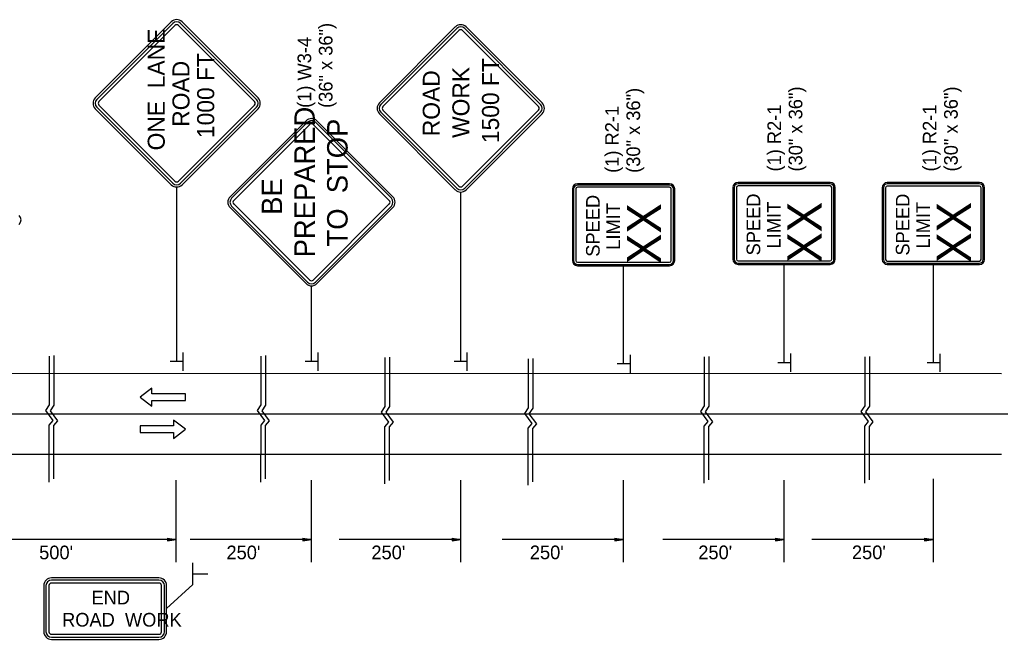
# Model space of a CAD drawing. Extents: x 1927831 to 1930787, y 596452 to 597699.
# Drawn here: x 1928053.9 to 1928485.3, y 596920.4 to 597192.8 of the extents above; entities that cross this region are included whole.
import ezdxf

# ---------------------------------------------------------------- set-up
doc = ezdxf.new("R2010")
doc.units = 0
for name, color, linetype in [('Default', 7, 'Continuous'), ('P_TC_Signs_Permanent', 7, 'Continuous'), ('P_TC_Signs_Temporary', 7, 'Continuous'), ('R_Annotation', 7, 'Continuous'), ('R_Striping', 7, 'Continuous')]:
    doc.layers.add(name, color=color, linetype=linetype)

msp = doc.modelspace()

# ---------------------------------------------------------------- linework, layer by layer
at = {"layer": 'Default'}
for p, q in [((1928125.67, 597046.42), (1928125.67, 597038.42)), ((1928185.12, 597046.42), (1928185.12, 597038.42)), ((1928250.6, 597046.42), (1928250.6, 597038.42)), ((1928322.37, 597045.39), (1928322.37, 597037.38)), ((1928392.98, 597045.97), (1928392.98, 597037.96)), ((1928458.63, 597045.91), (1928458.63, 597037.91)), ((1928125.55, 597042.44), (1928120.09, 597042.44)), ((1928185.01, 597042.44), (1928179.54, 597042.44)), ((1928250.48, 597042.44), (1928245.02, 597042.44)), ((1928322.25, 597041.41), (1928316.79, 597041.41)), ((1928392.86, 597041.99), (1928387.4, 597041.99)), ((1928458.51, 597041.93), (1928453.05, 597041.93)), ((1927841.07, 597037.34), (1928485.68, 597037.29)), ((1927840.35, 597019.55), (1928622.79, 597019.49)), ((1927840.85, 597001.76), (1928485.68, 597001.71)), ((1928122.82, 596954.25), (1928122.82, 596990.28)), ((1928182.27, 596954.25), (1928182.27, 596990.28)), ((1928247.93, 596954.25), (1928247.93, 596990.28)), ((1928319.52, 596954.25), (1928319.52, 596990.28)), ((1928390.13, 596954.25), (1928390.13, 596990.28)), ((1928455.78, 596954.25), (1928455.78, 596990.96)), ((1928122.82, 596964.29), (1928023.06, 596964.29)), ((1928118.98, 596964.87), (1928122.82, 596964.29)), ((1928118.98, 596964.87), (1928118.98, 596963.71)), ((1928118.98, 596964.77), (1928122.18, 596964.29)), ((1928118.98, 596964.67), (1928121.52, 596964.29)), ((1928118.98, 596964.58), (1928120.88, 596964.29)), ((1928118.98, 596964.48), (1928120.23, 596964.29)), ((1928118.98, 596964.38), (1928119.59, 596964.29)), ((1928118.98, 596963.71), (1928122.82, 596964.29)), ((1928118.98, 596964.1), (1928120.23, 596964.29)), ((1928118.98, 596963.91), (1928121.52, 596964.29)), ((1928118.98, 596963.81), (1928122.18, 596964.29)), ((1928118.98, 596964), (1928120.88, 596964.29)), ((1928118.98, 596964.2), (1928119.59, 596964.29)), ((1928182.27, 596964.29), (1928128.87, 596964.29)), ((1928178.44, 596964.87), (1928182.27, 596964.29)), ((1928178.44, 596964.87), (1928178.44, 596963.71)), ((1928178.44, 596964.77), (1928181.63, 596964.29)), ((1928178.44, 596964.67), (1928180.97, 596964.29)), ((1928178.44, 596964.58), (1928180.33, 596964.29)), ((1928178.44, 596964.48), (1928179.68, 596964.29)), ((1928178.44, 596964.38), (1928179.04, 596964.29)), ((1928178.44, 596963.71), (1928182.27, 596964.29)), ((1928178.44, 596964.1), (1928179.68, 596964.29)), ((1928178.44, 596963.91), (1928180.97, 596964.29)), ((1928178.44, 596963.81), (1928181.63, 596964.29)), ((1928178.44, 596964), (1928180.33, 596964.29)), ((1928178.44, 596964.2), (1928179.04, 596964.29)), ((1928247.93, 596964.29), (1928194.52, 596964.29)), ((1928244.09, 596964.87), (1928247.93, 596964.29)), ((1928244.09, 596964.87), (1928244.09, 596963.71)), ((1928244.09, 596964.77), (1928247.29, 596964.29)), ((1928244.09, 596964.67), (1928246.63, 596964.29)), ((1928244.09, 596964.58), (1928245.99, 596964.29)), ((1928244.09, 596964.48), (1928245.34, 596964.29)), ((1928244.09, 596964.38), (1928244.7, 596964.29)), ((1928244.09, 596963.71), (1928247.93, 596964.29)), ((1928244.09, 596964.1), (1928245.34, 596964.29)), ((1928244.09, 596963.91), (1928246.63, 596964.29)), ((1928244.09, 596963.81), (1928247.29, 596964.29)), ((1928244.09, 596964), (1928245.99, 596964.29)), ((1928244.09, 596964.2), (1928244.7, 596964.29)), ((1928319.52, 596964.29), (1928266.12, 596964.29)), ((1928315.68, 596964.87), (1928319.52, 596964.29)), ((1928315.68, 596964.87), (1928315.68, 596963.71)), ((1928315.68, 596964.77), (1928318.88, 596964.29)), ((1928315.68, 596964.67), (1928318.22, 596964.29)), ((1928315.68, 596964.58), (1928317.58, 596964.29)), ((1928315.68, 596964.48), (1928316.93, 596964.29)), ((1928315.68, 596964.38), (1928316.29, 596964.29)), ((1928315.68, 596963.71), (1928319.52, 596964.29)), ((1928315.68, 596964.1), (1928316.93, 596964.29)), ((1928315.68, 596963.91), (1928318.22, 596964.29)), ((1928315.68, 596963.81), (1928318.88, 596964.29)), ((1928315.68, 596964), (1928317.58, 596964.29)), ((1928315.68, 596964.2), (1928316.29, 596964.29)), ((1928390.13, 596964.29), (1928336.73, 596964.29)), ((1928386.29, 596964.87), (1928390.13, 596964.29)), ((1928386.29, 596964.87), (1928386.29, 596963.71)), ((1928386.29, 596964.77), (1928389.49, 596964.29)), ((1928386.29, 596964.67), (1928388.83, 596964.29)), ((1928386.29, 596964.58), (1928388.19, 596964.29)), ((1928386.29, 596964.48), (1928387.54, 596964.29)), ((1928386.29, 596964.38), (1928386.9, 596964.29)), ((1928386.29, 596963.71), (1928390.13, 596964.29)), ((1928386.29, 596964.1), (1928387.54, 596964.29)), ((1928386.29, 596963.91), (1928388.83, 596964.29)), ((1928386.29, 596963.81), (1928389.49, 596964.29)), ((1928386.29, 596964), (1928388.19, 596964.29)), ((1928386.29, 596964.2), (1928386.9, 596964.29)), ((1928455.78, 596964.29), (1928402.38, 596964.29)), ((1928451.94, 596964.87), (1928455.78, 596964.29)), ((1928451.94, 596964.87), (1928451.94, 596963.71)), ((1928451.94, 596964.77), (1928455.14, 596964.29)), ((1928451.94, 596964.67), (1928454.48, 596964.29)), ((1928451.94, 596964.58), (1928453.84, 596964.29)), ((1928451.94, 596964.48), (1928453.19, 596964.29)), ((1928451.94, 596964.38), (1928452.55, 596964.29)), ((1928451.94, 596963.71), (1928455.78, 596964.29)), ((1928451.94, 596964.1), (1928453.19, 596964.29)), ((1928451.94, 596963.91), (1928454.48, 596964.29)), ((1928451.94, 596963.81), (1928455.14, 596964.29)), ((1928451.94, 596964), (1928453.84, 596964.29)), ((1928451.94, 596964.2), (1928452.55, 596964.29)), ((1928130.08, 596944.51), (1928130.08, 596954)), ((1928130.22, 596949.23), (1928136.7, 596949.23)), ((1928130.08, 596944.51), (1928118.55, 596933.86))]:
    msp.add_line(p, q, dxfattribs=at)
for points in [[(1928066.89, 597044.92), (1928066.89, 597023.4), (1928065.23, 597020.93), (1928068.47, 597016.5), (1928066.76, 597014.45), (1928066.76, 596989.43)], [(1928068.93, 597045.12), (1928068.93, 597023.32), (1928067.27, 597020.84), (1928070.51, 597016.41), (1928068.81, 597014.37), (1928068.8, 596990.87)], [(1928160.05, 597044.92), (1928160.05, 597023.4), (1928158.39, 597020.93), (1928161.63, 597016.5), (1928159.93, 597014.45), (1928159.92, 596989.43)], [(1928162.1, 597045.12), (1928162.1, 597023.32), (1928160.44, 597020.84), (1928163.67, 597016.41), (1928161.97, 597014.37), (1928161.97, 596990.87)], [(1928214.52, 597044.28), (1928214.52, 597022.75), (1928212.85, 597020.28), (1928216.09, 597015.85), (1928214.39, 597013.81), (1928214.38, 596988.78)], [(1928216.56, 597044.47), (1928216.56, 597022.67), (1928214.9, 597020.2), (1928218.14, 597015.77), (1928216.43, 597013.72), (1928216.43, 596990.22)], [(1928277.56, 597043.61), (1928277.56, 597022.08), (1928275.9, 597019.61), (1928279.13, 597015.18), (1928277.43, 597013.14), (1928277.42, 596988.11)], [(1928279.6, 597043.8), (1928279.6, 597022), (1928277.94, 597019.53), (1928281.18, 597015.1), (1928279.47, 597013.05), (1928279.47, 596989.55)], [(1928355, 597044.49), (1928355, 597022.97), (1928353.34, 597020.5), (1928356.57, 597016.07), (1928354.87, 597014.02), (1928354.86, 596989)], [(1928357.04, 597044.69), (1928357.04, 597022.88), (1928355.38, 597020.41), (1928358.62, 597015.98), (1928356.91, 597013.94), (1928356.91, 596990.44)], [(1928425.61, 597044.49), (1928425.61, 597022.97), (1928423.95, 597020.5), (1928427.18, 597016.07), (1928425.48, 597014.02), (1928425.47, 596989)], [(1928427.65, 597044.69), (1928427.65, 597022.88), (1928425.99, 597020.41), (1928429.23, 597015.98), (1928427.52, 597013.94), (1928427.52, 596990.44)]]:
    msp.add_lwpolyline(points, dxfattribs=at)
at = {"layer": 'P_TC_Signs_Permanent'}
for p, q in [((1928179.89, 597148.33), (1928146.48, 597114.92)), ((1928180.55, 597147.67), (1928147.14, 597114.25)), ((1928181.48, 597146.74), (1928148.07, 597113.33)), ((1928216.48, 597113.33), (1928183.07, 597146.74)), ((1928217.41, 597114.25), (1928184, 597147.67)), ((1928218.07, 597114.92), (1928184.66, 597148.33)), ((1928339.77, 597120.63), (1928299.27, 597120.63)), ((1928339.77, 597120.07), (1928299.27, 597120.07)), ((1928339.77, 597119.13), (1928299.27, 597119.13)), ((1928367.63, 597118.96), (1928367.63, 597087.46)), ((1928368.19, 597118.96), (1928368.19, 597087.46)), ((1928369.13, 597118.96), (1928369.13, 597087.46)), ((1928410.38, 597121.21), (1928369.88, 597121.21)), ((1928410.38, 597120.65), (1928369.88, 597120.65)), ((1928410.38, 597119.71), (1928369.88, 597119.71)), ((1928411.13, 597087.46), (1928411.13, 597118.96)), ((1928412.07, 597087.46), (1928412.07, 597118.96)), ((1928412.63, 597087.46), (1928412.63, 597118.96)), ((1928433.28, 597118.9), (1928433.28, 597087.4)), ((1928433.84, 597118.9), (1928433.84, 597087.4)), ((1928434.78, 597118.9), (1928434.78, 597087.4)), ((1928476.03, 597121.15), (1928435.53, 597121.15)), ((1928476.03, 597120.59), (1928435.53, 597120.59)), ((1928476.03, 597119.65), (1928435.53, 597119.65)), ((1928476.78, 597087.4), (1928476.78, 597118.9)), ((1928477.72, 597087.4), (1928477.72, 597118.9)), ((1928478.28, 597087.4), (1928478.28, 597118.9)), ((1928297.02, 597118.38), (1928297.02, 597086.88)), ((1928297.58, 597118.38), (1928297.58, 597086.88)), ((1928298.52, 597118.38), (1928298.52, 597086.88)), ((1928340.52, 597086.88), (1928340.52, 597118.38)), ((1928341.46, 597086.88), (1928341.46, 597118.38)), ((1928342.02, 597086.88), (1928342.02, 597118.38)), ((1928146.48, 597110.14), (1928179.89, 597076.73)), ((1928147.14, 597110.81), (1928180.55, 597077.4)), ((1928148.07, 597111.74), (1928181.48, 597078.32)), ((1928183.07, 597078.32), (1928216.48, 597111.74)), ((1928184, 597077.4), (1928217.41, 597110.81)), ((1928184.66, 597076.73), (1928218.07, 597110.14)), ((1928299.27, 597086.13), (1928339.77, 597086.13)), ((1928299.27, 597085.19), (1928339.77, 597085.19)), ((1928299.27, 597084.63), (1928339.77, 597084.63)), ((1928369.88, 597086.71), (1928410.38, 597086.71)), ((1928369.88, 597085.77), (1928410.38, 597085.77)), ((1928369.88, 597085.21), (1928410.38, 597085.21)), ((1928435.53, 597086.65), (1928476.03, 597086.65)), ((1928435.53, 597085.71), (1928476.03, 597085.71)), ((1928435.53, 597085.15), (1928476.03, 597085.15))]:
    msp.add_line(p, q, dxfattribs=at)
for centre, radius, start, end in [((1928182.27, 597145.94), 3.37, 45, 135), ((1928182.27, 597145.94), 2.44, 45, 135), ((1928182.27, 597145.94), 1.13, 45, 135), ((1928299.27, 597118.38), 2.25, 90, 180), ((1928299.27, 597118.38), 1.69, 90, 180), ((1928299.27, 597118.38), 0.75, 90, 180), ((1928339.77, 597118.38), 2.25, 360, 90), ((1928339.77, 597118.38), 1.69, 360, 90), ((1928339.77, 597118.38), 0.75, 360, 90), ((1928369.88, 597118.96), 2.25, 90, 180), ((1928369.88, 597118.96), 1.69, 90, 180), ((1928369.88, 597118.96), 0.75, 90, 180), ((1928410.38, 597118.96), 2.25, 360, 90), ((1928410.38, 597118.96), 1.69, 360, 90), ((1928410.38, 597118.96), 0.75, 360, 90), ((1928435.53, 597118.9), 2.25, 90, 180), ((1928435.53, 597118.9), 1.69, 90, 180), ((1928435.53, 597118.9), 0.75, 90, 180), ((1928476.03, 597118.9), 2.25, 360, 90), ((1928476.03, 597118.9), 1.69, 360, 90), ((1928476.03, 597118.9), 0.75, 360, 90), ((1928148.86, 597112.53), 3.37, 135, 225), ((1928215.68, 597112.53), 3.37, 315, 45), ((1928148.86, 597112.53), 2.44, 135, 225), ((1928148.86, 597112.53), 1.13, 135, 225), ((1928215.68, 597112.53), 1.13, 315, 45), ((1928215.68, 597112.53), 2.44, 315, 45), ((1928051.76, 597104.75), 2.81, 315, 45), ((1928299.27, 597086.88), 2.25, 180, 270), ((1928299.27, 597086.88), 1.69, 180, 270), ((1928299.27, 597086.88), 0.75, 180, 270), ((1928339.77, 597086.88), 2.25, 270, 360), ((1928339.77, 597086.88), 1.69, 270, 360), ((1928339.77, 597086.88), 0.75, 270, 360), ((1928369.88, 597087.46), 2.25, 180, 270), ((1928369.88, 597087.46), 1.69, 180, 270), ((1928369.88, 597087.46), 0.75, 180, 270), ((1928410.38, 597087.46), 2.25, 270, 360), ((1928410.38, 597087.46), 1.69, 270, 360), ((1928410.38, 597087.46), 0.75, 270, 360), ((1928435.53, 597087.4), 2.25, 180, 270), ((1928435.53, 597087.4), 1.69, 180, 270), ((1928435.53, 597087.4), 0.75, 180, 270), ((1928476.03, 597087.4), 2.25, 270, 360), ((1928476.03, 597087.4), 1.69, 270, 360), ((1928476.03, 597087.4), 0.75, 270, 360), ((1928182.27, 597079.12), 3.37, 225, 315), ((1928182.27, 597079.12), 2.44, 225, 315), ((1928182.27, 597079.12), 1.13, 225, 315)]:
    msp.add_arc(centre, radius, start, end, dxfattribs=at)
at = {"layer": 'P_TC_Signs_Temporary'}
for p, q in [((1928087.2, 597158.38), (1928120.61, 597191.8)), ((1928087.86, 597157.72), (1928121.27, 597191.13)), ((1928088.79, 597156.79), (1928122.2, 597190.2)), ((1928123.79, 597190.2), (1928157.2, 597156.79)), ((1928124.72, 597191.13), (1928158.13, 597157.72)), ((1928125.38, 597191.8), (1928158.79, 597158.38)), ((1928212.13, 597156.16), (1928245.54, 597189.57)), ((1928212.79, 597155.5), (1928246.2, 597188.91)), ((1928213.72, 597154.57), (1928247.13, 597187.98)), ((1928248.72, 597187.98), (1928282.13, 597154.57)), ((1928249.65, 597188.91), (1928283.06, 597155.5)), ((1928250.31, 597189.57), (1928283.72, 597156.16)), ((1928120.61, 597120.2), (1928087.2, 597153.61)), ((1928121.27, 597120.86), (1928087.86, 597154.27)), ((1928122.2, 597121.79), (1928088.79, 597155.2)), ((1928157.2, 597155.2), (1928123.79, 597121.79)), ((1928158.13, 597154.27), (1928124.72, 597120.86)), ((1928158.79, 597153.61), (1928125.38, 597120.2)), ((1928245.54, 597117.98), (1928212.13, 597151.39)), ((1928246.2, 597118.64), (1928212.79, 597152.05)), ((1928247.13, 597119.57), (1928213.72, 597152.98)), ((1928282.13, 597152.98), (1928248.72, 597119.57)), ((1928283.06, 597152.05), (1928249.65, 597118.64)), ((1928283.72, 597151.39), (1928250.31, 597117.98)), ((1928115.18, 596947.36), (1928067.93, 596947.36)), ((1928115.18, 596946.42), (1928067.93, 596946.42)), ((1928064.55, 596943.99), (1928064.55, 596923.74)), ((1928065.49, 596943.99), (1928065.49, 596923.74)), ((1928066.8, 596943.99), (1928066.8, 596923.74)), ((1928115.18, 596945.11), (1928067.93, 596945.11)), ((1928116.3, 596923.74), (1928116.3, 596943.99)), ((1928117.61, 596923.74), (1928117.61, 596943.99)), ((1928118.55, 596923.74), (1928118.55, 596943.99)), ((1928067.93, 596922.61), (1928115.18, 596922.61)), ((1928067.93, 596921.3), (1928115.18, 596921.3)), ((1928067.93, 596920.36), (1928115.18, 596920.36))]:
    msp.add_line(p, q, dxfattribs=at)
for centre, radius, start, end in [((1928122.99, 597189.41), 3.37, 45, 135), ((1928122.99, 597189.41), 2.44, 45, 135), ((1928122.99, 597189.41), 1.12, 45, 135), ((1928247.93, 597187.19), 3.37, 45, 135), ((1928247.93, 597187.19), 2.44, 45, 135), ((1928247.93, 597187.19), 1.12, 45, 135), ((1928089.58, 597156), 3.37, 135, 225), ((1928089.58, 597156), 2.44, 135, 225), ((1928156.4, 597156), 2.44, 315, 45), ((1928156.4, 597156), 3.37, 315, 45), ((1928089.58, 597156), 1.13, 135, 225), ((1928156.4, 597156), 1.13, 315, 45), ((1928214.52, 597153.78), 3.37, 135, 225), ((1928214.52, 597153.78), 2.44, 135, 225), ((1928214.52, 597153.78), 1.13, 135, 225), ((1928281.34, 597153.78), 1.13, 315, 45), ((1928281.34, 597153.78), 2.44, 315, 45), ((1928281.34, 597153.78), 3.37, 315, 45), ((1928122.99, 597122.59), 3.37, 225, 315), ((1928122.99, 597122.59), 2.44, 225, 315), ((1928122.99, 597122.59), 1.12, 225, 315), ((1928247.93, 597120.37), 2.44, 225, 315), ((1928247.93, 597120.37), 1.12, 225, 315), ((1928247.93, 597120.37), 3.37, 225, 315), ((1928067.93, 596943.99), 3.37, 90, 180), ((1928067.93, 596943.99), 2.44, 90, 180), ((1928115.18, 596943.99), 3.38, 0, 90), ((1928115.18, 596943.99), 2.44, 0, 90), ((1928067.93, 596943.99), 1.13, 90, 180), ((1928115.18, 596943.99), 1.13, 0, 90), ((1928067.93, 596923.74), 3.38, 180, 270), ((1928067.93, 596923.74), 2.44, 180, 270), ((1928067.93, 596923.74), 1.13, 180, 270), ((1928115.18, 596923.74), 2.44, 270, 0), ((1928115.18, 596923.74), 1.13, 270, 0), ((1928115.18, 596923.74), 3.37, 270, 0)]:
    msp.add_arc(centre, radius, start, end, dxfattribs=at)
at = {"layer": 'R_Annotation'}
for p, q in [((1928122.99, 597042.44), (1928122.99, 597119.21)), ((1928247.93, 597042.44), (1928247.93, 597116.99)), ((1928319.52, 597041.41), (1928319.52, 597084.63)), ((1928390.13, 597041.99), (1928390.13, 597085.21)), ((1928455.78, 597041.93), (1928455.78, 597085.15)), ((1928182.27, 597042.44), (1928182.27, 597075.74))]:
    msp.add_line(p, q, dxfattribs=at)
at = {"layer": 'R_Striping'}
for points in [[(1928112.09, 597030.85), (1928106.9, 597026.85), (1928112.09, 597022.85), (1928112.09, 597025.35), (1928126.8, 597025.35), (1928126.8, 597028.35), (1928112.09, 597028.35)], [(1928121.61, 597008.73), (1928126.8, 597012.73), (1928121.61, 597016.73), (1928121.61, 597014.23), (1928106.9, 597014.23), (1928106.9, 597011.23), (1928121.61, 597011.23)]]:
    msp.add_lwpolyline(points, close=True, dxfattribs=at)

# ---------------------------------------------------------------- texts
at = {"layer": 'Default'}
for s, p in [("500'", (1928062.5, 596955.57)), ("250'", (1928144.88, 596955.58)), ("250'", (1928208.62, 596955.59)), ("250'", (1928278.31, 596955.6)), ("250'", (1928352.39, 596955.61)), ("250'", (1928419.97, 596955.62))]:
    msp.add_text(s, height=6, rotation=359.9922, dxfattribs=at).set_placement(p)
at = {"layer": 'P_TC_Signs_Permanent'}
for s, height, p in [('SPEED', 6, (1928309.02, 597088.56)), ('SPEED', 6, (1928379.63, 597089.14)), ('SPEED', 6, (1928445.28, 597089.08)), ('LIMIT', 6, (1928318.02, 597091.65)), ('XX', 15, (1928336.02, 597085.33)), ('LIMIT', 6, (1928388.63, 597092.23)), ('XX', 15, (1928406.63, 597085.91)), ('LIMIT', 6, (1928454.28, 597092.17)), ('XX', 15, (1928472.28, 597085.85))]:
    msp.add_text(s, height=height, rotation=90, dxfattribs=at).set_placement(p)
at = {"layer": 'P_TC_Signs_Temporary'}
for s, height, p in [('ONE  LANE', 7.5, (1928117.74, 597135.3)), ('1000 FT', 7.5, (1928139.49, 597140.71)), ('1500 FT', 7.5, (1928264.76, 597138.49)), ('ROAD', 7.5, (1928128.62, 597145.69)), ('WORK', 7.5, (1928251.74, 597140.79)), (' ROAD ', 7.5, (1928238.71, 597138.75)), ('PREPARED', 9, (1928183.75, 597088.29)), ('TO  STOP', 9, (1928198.15, 597093.07)), ('BE', 9, (1928169.35, 597106.98))]:
    msp.add_text(s, height=height, rotation=90, dxfattribs=at).set_placement(p)
for s, p in [('END', (1928085.52, 596935.74)), ('ROAD  WORK', (1928072.59, 596925.99))]:
    msp.add_text(s, height=6, dxfattribs=at).set_placement(p)
at = {"layer": 'R_Annotation'}
for s, height, p in [('(36" x 36")', 5.9996, (1928191.51, 597153.98)), ('(1) W3-4', 6, (1928182.14, 597153.98)), ('(30" x 36")', 5.9996, (1928326.8, 597125.43)), ('(30" x 36")', 5.9996, (1928398.16, 597126.03)), ('(30" x 36")', 5.9996, (1928466.5, 597126.03)), ('(1) R2-1', 6, (1928317.44, 597125.43)), ('(1) R2-1', 6, (1928388.8, 597126.03)), ('(1) R2-1', 6, (1928457.14, 597126.03))]:
    msp.add_text(s, height=height, rotation=90, dxfattribs=at).set_placement(p)

doc.saveas('drawing.dxf')
